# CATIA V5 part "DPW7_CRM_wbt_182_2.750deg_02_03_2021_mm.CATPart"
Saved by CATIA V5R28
Part number: DPW7_CRM_wbt_182_2.750deg_02_03_2021
Bounding box of the stored display mesh (mm): x 2349.5 to 66711.891, y 0 to 29452.621, z 2310.119 to 8715.756
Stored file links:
  Z:\Scratch\04_CAD_Allgemein\Flight2Jig\Output\DPW-7\CATPart\DPW7_CRM_wbt_182_2.750deg_02_03_2021.CATPart
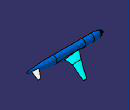
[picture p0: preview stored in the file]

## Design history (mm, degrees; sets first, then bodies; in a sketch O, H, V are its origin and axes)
Set1
  DatumSurface1 "Clean_Wing"
  DatumSurface2 "Fuselage"
  DatumSurface3 "HTP"
  DatumSurface4 "Symmetry"
  DatumSurface5 "Farfield"
Body1 (main body)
